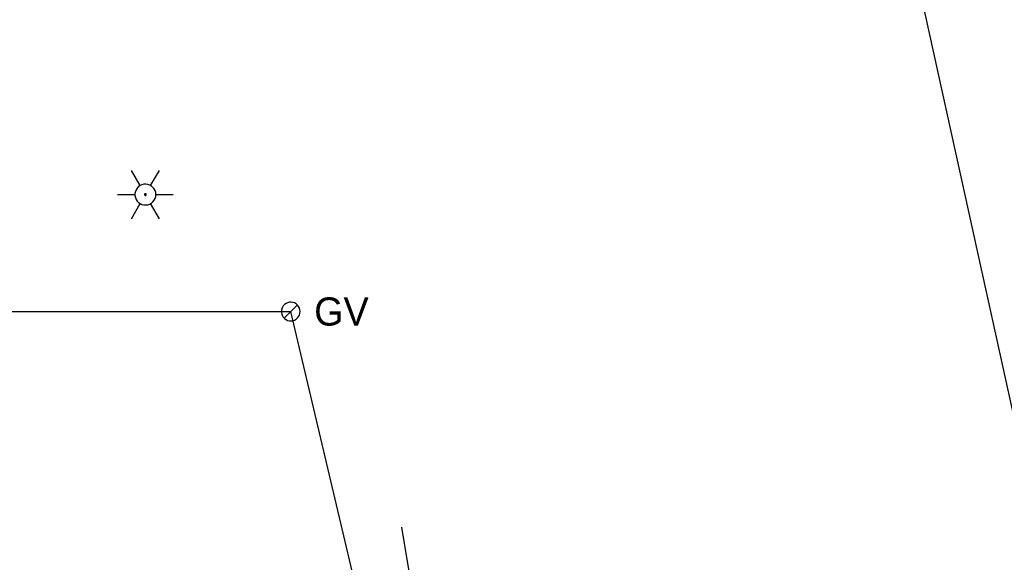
# Model space of a CAD drawing. Extents: x 596028 to 606371, y 330010 to 403088.
# Drawn here: x 604936.2 to 605070.6, y 350036.3 to 350110.5 of the extents above; entities that cross this region are included whole.
import ezdxf

# ---------------------------------------------------------------- set-up
doc = ezdxf.new("R2010")
doc.units = 0
for name, color, linetype in [('E_LTG', 7, 'Continuous'), ('E_UTL_G', 7, 'Continuous'), ('E_UTL_G_UG', 7, 'Continuous'), ('E_UTL_SAN_UG', 7, 'Continuous'), ('E_UTL_TV_UG', 7, 'Continuous')]:
    doc.layers.add(name, color=color, linetype=linetype)

# ---------------------------------------------------------------- blocks, each defined once
blk = doc.blocks.new('ACAD_PROXY_ENTITY_15')
at = {"layer": 'E_LTG'}
for points in [[(1843663.8, 1030159.59), (1843660.17, 1030165.87)], [(1843668.16, 1030159.59), (1843671.79, 1030165.87)], [(1843670.34, 1030155.82), (1843670.26, 1030156.64), (1843670.02, 1030157.44), (1843669.64, 1030158.17), (1843669.13, 1030158.82), (1843668.51, 1030159.36), (1843667.79, 1030159.78), (1843667.01, 1030160.05), (1843666.19, 1030160.17), (1843665.36, 1030160.13), (1843664.56, 1030159.93), (1843663.8, 1030159.59), (1843663.13, 1030159.11), (1843662.56, 1030158.51), (1843662.11, 1030157.81), (1843661.8, 1030157.04), (1843661.64, 1030156.23), (1843661.64, 1030155.4), (1843661.8, 1030154.59), (1843662.11, 1030153.82), (1843662.56, 1030153.12), (1843663.13, 1030152.52), (1843663.8, 1030152.04), (1843664.56, 1030151.7), (1843665.36, 1030151.51), (1843666.19, 1030151.47), (1843667.01, 1030151.58), (1843667.79, 1030151.85), (1843668.51, 1030152.27), (1843669.13, 1030152.81), (1843669.64, 1030153.46), (1843670.02, 1030154.2), (1843670.26, 1030154.99), (1843670.34, 1030155.82)], [(1843670.34, 1030155.82), (1843670.26, 1030156.64), (1843670.02, 1030157.44), (1843669.64, 1030158.17), (1843669.13, 1030158.82), (1843668.51, 1030159.36), (1843667.79, 1030159.78), (1843667.01, 1030160.05), (1843666.19, 1030160.17), (1843665.36, 1030160.13), (1843664.56, 1030159.93), (1843663.8, 1030159.59), (1843663.13, 1030159.11), (1843662.56, 1030158.51), (1843662.11, 1030157.81), (1843661.8, 1030157.04), (1843661.64, 1030156.23), (1843661.64, 1030155.4), (1843661.8, 1030154.59), (1843662.11, 1030153.82), (1843662.56, 1030153.12), (1843663.13, 1030152.52), (1843663.8, 1030152.04), (1843664.56, 1030151.7), (1843665.36, 1030151.51), (1843666.19, 1030151.47), (1843667.01, 1030151.58), (1843667.79, 1030151.85), (1843668.51, 1030152.27), (1843669.13, 1030152.81), (1843669.64, 1030153.46), (1843670.02, 1030154.2), (1843670.26, 1030154.99), (1843670.34, 1030155.82)], [(1843670.34, 1030155.82), (1843670.26, 1030156.64), (1843670.02, 1030157.44), (1843669.64, 1030158.17), (1843669.13, 1030158.82), (1843668.51, 1030159.36), (1843667.79, 1030159.78), (1843667.01, 1030160.05), (1843666.19, 1030160.17), (1843665.36, 1030160.13), (1843664.56, 1030159.93), (1843663.8, 1030159.59), (1843663.13, 1030159.11), (1843662.56, 1030158.51), (1843662.11, 1030157.81), (1843661.8, 1030157.04), (1843661.64, 1030156.23), (1843661.64, 1030155.4), (1843661.8, 1030154.59), (1843662.11, 1030153.82), (1843662.56, 1030153.12), (1843663.13, 1030152.52), (1843663.8, 1030152.04), (1843664.56, 1030151.7), (1843665.36, 1030151.51), (1843666.19, 1030151.47), (1843667.01, 1030151.58), (1843667.79, 1030151.85), (1843668.51, 1030152.27), (1843669.13, 1030152.81), (1843669.64, 1030153.46), (1843670.02, 1030154.2), (1843670.26, 1030154.99), (1843670.34, 1030155.82)], [(1843666.34, 1030155.82), (1843666.34, 1030155.88), (1843666.32, 1030155.95), (1843666.29, 1030156.01), (1843666.24, 1030156.07), (1843666.19, 1030156.11), (1843666.13, 1030156.15), (1843666.07, 1030156.17), (1843666, 1030156.18), (1843665.93, 1030156.18), (1843665.86, 1030156.16), (1843665.8, 1030156.13), (1843665.74, 1030156.09), (1843665.69, 1030156.04), (1843665.66, 1030155.98), (1843665.63, 1030155.92), (1843665.62, 1030155.85), (1843665.62, 1030155.78), (1843665.63, 1030155.71), (1843665.66, 1030155.65), (1843665.69, 1030155.59), (1843665.74, 1030155.54), (1843665.8, 1030155.5), (1843665.86, 1030155.47), (1843665.93, 1030155.46), (1843666, 1030155.45), (1843666.07, 1030155.46), (1843666.13, 1030155.49), (1843666.19, 1030155.52), (1843666.24, 1030155.57), (1843666.29, 1030155.62), (1843666.32, 1030155.68), (1843666.34, 1030155.75), (1843666.34, 1030155.82)], [(1843654.37, 1030155.82), (1843661.62, 1030155.82)], [(1843660.17, 1030145.76), (1843663.8, 1030152.04)], [(1843671.79, 1030145.76), (1843668.16, 1030152.04)], [(1843670.34, 1030155.82), (1843677.59, 1030155.82)]]:
    blk.add_lwpolyline(points, dxfattribs=at)

msp = doc.modelspace()

# ---------------------------------------------------------------- linework, layer by layer
at = {"layer": 'E_UTL_G'}
for points in [[(604974.45, 350070.59), (604974.42, 350070.83), (604974.35, 350071.07), (604974.24, 350071.28), (604974.09, 350071.48), (604973.91, 350071.64), (604973.7, 350071.76), (604973.47, 350071.84), (604973.22, 350071.87), (604972.98, 350071.86), (604972.74, 350071.8), (604972.52, 350071.7), (604972.32, 350071.56), (604972.15, 350071.38), (604972.02, 350071.18), (604971.93, 350070.95), (604971.89, 350070.71), (604971.89, 350070.47), (604971.93, 350070.23), (604972.02, 350070), (604972.15, 350069.8), (604972.32, 350069.62), (604972.52, 350069.48), (604972.74, 350069.38), (604972.98, 350069.32), (604973.22, 350069.31), (604973.47, 350069.34), (604973.7, 350069.42), (604973.91, 350069.55), (604974.09, 350069.71), (604974.24, 350069.9), (604974.35, 350070.11), (604974.42, 350070.35), (604974.45, 350070.59)], [(604972.26, 350069.68), (604974.07, 350071.5)]]:
    msp.add_lwpolyline(points, dxfattribs=at)
at = {"layer": 'E_UTL_G_UG'}
for points in [[(604862.13, 350070.59), (604973.16, 350070.59)], [(604944.96, 349967.84), (604968.33, 349976.55), (604971.11, 349977.02), (604975.73, 349980.5), (604985.67, 349985.89), (604988.78, 350004.44), (604973.16, 350070.59)]]:
    msp.add_lwpolyline(points, dxfattribs=at)
at = {"layer": 'E_UTL_SAN_UG'}
msp.add_lwpolyline([(605091.22, 349968.71), (605057.94, 350119.84)], dxfattribs=at)
at = {"layer": 'E_UTL_TV_UG'}
msp.add_lwpolyline([(604988.28, 350041.13), (604990.53, 350027.64), (604989.92, 350014.96), (604987.9, 350003.51), (604983.08, 349994.32), (604974.67, 349986.39), (604969.91, 349979.91), (604965.32, 349981.81), (604959.93, 349983.92), (604950.62, 349983.67), (604917.59, 349983.57)], dxfattribs=at)

# ---------------------------------------------------------------- block references
at = {"layer": 'E_LTG', "xscale": 0.32808333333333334, "yscale": 0.32808333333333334}
msp.add_blockref('ACAD_PROXY_ENTITY_15', (77.24, 12109.62), dxfattribs=at)

# ---------------------------------------------------------------- texts
at = {"layer": 'E_UTL_G'}
msp.add_text('GV', height=3.85, dxfattribs=at).set_placement((604976.37, 350068.67))

doc.saveas('drawing.dxf')
